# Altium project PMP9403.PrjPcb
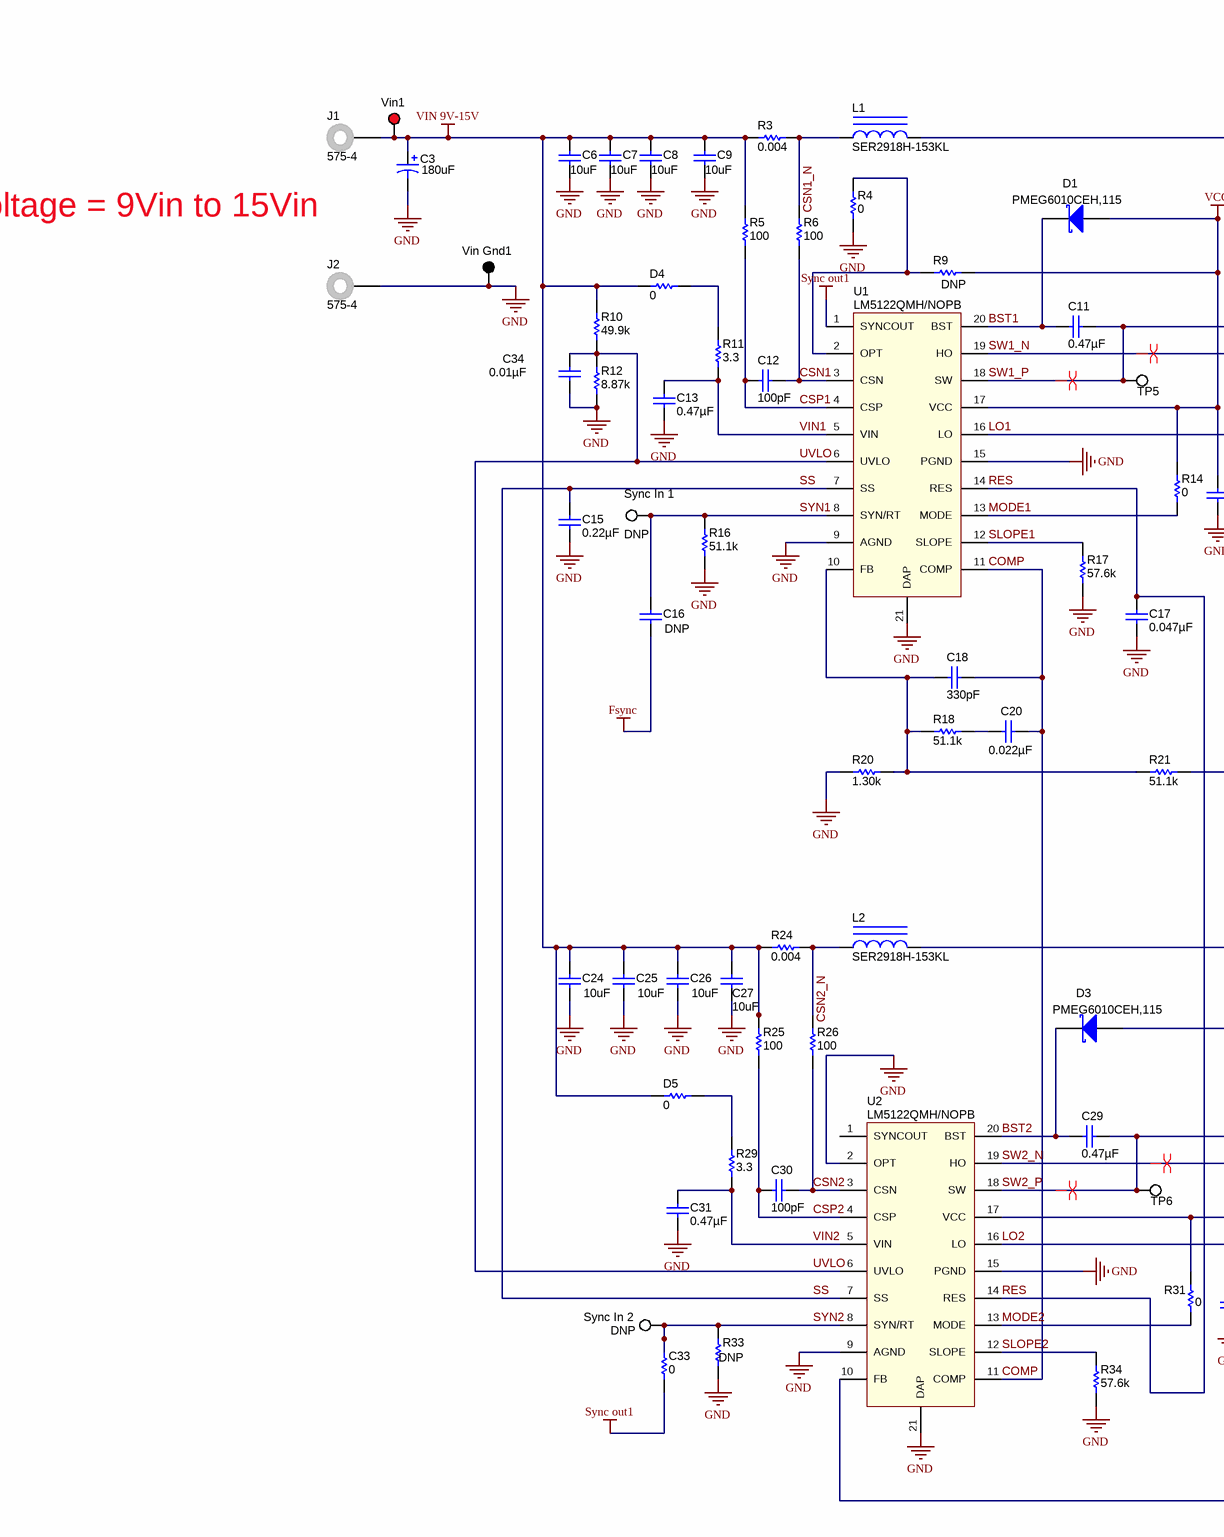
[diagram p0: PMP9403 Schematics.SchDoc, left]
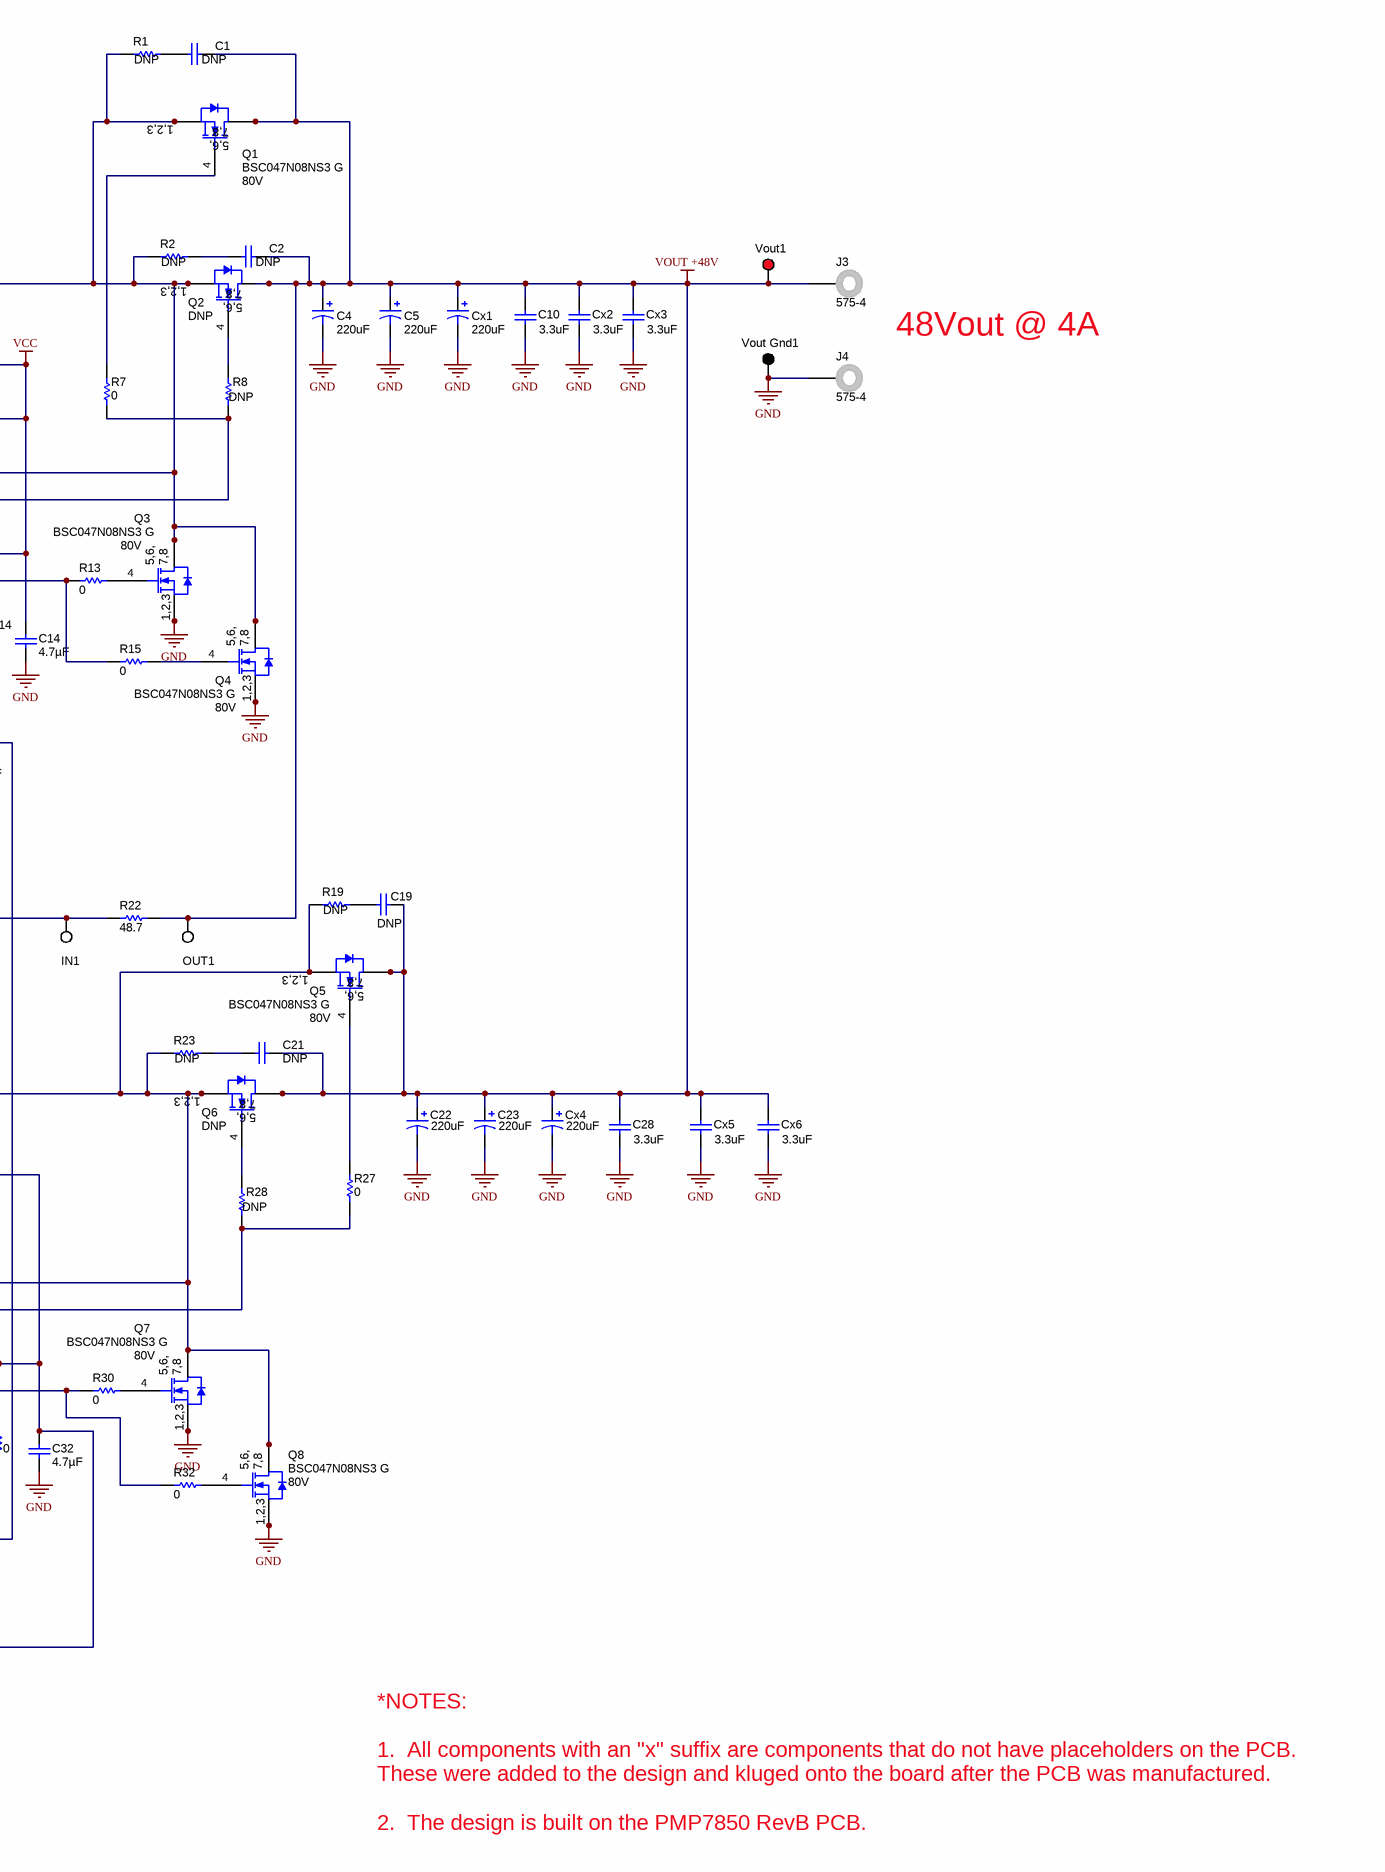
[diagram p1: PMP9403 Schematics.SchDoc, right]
TID: PMP9403; TechSupport: http://www.ti.com/support; SCH_Rev: A; PRJ_Title: LM5122 Dual-Phase Synchronous Boost; PRJ_Number: PMP9403; PRJ_Engineer: Hrag Kasparian; PRJ_Customer: Public Release; PCB_RevB: B; PCB_Layout: N/A; EVM_Orderable: N/A; CopyrightYear: 2015
2 sheets, 113 parts. Net scope: global (net labels, ports and power ports of the same name join across sheets).
Board file: PMP7850 REVB.PcbDoc
Sheets:
  PMP9403 Schematics.SchDoc
  PMP9403_TID_Hardware.SchDoc

## Sheet PMP9403 Schematics.SchDoc: Schematic
size 558 x 431 mm; Date: Not shown in title block; ApprovedBy: Not shown in title block; CheckedBy: Not shown in title block; Author: Not shown in title block; CompanyName: Not shown in title block; Engineer: Not shown in title block; Organization: Not shown in title block; Address1: Not shown in title block; Address2: Not shown in title block; Address3: Not shown in title block; Address4: Not shown in title block; DocumentNumber: 1; Revision: Use project parameter SCH_Rev; SheetNumber: 1; SheetTotal: 2; PageSetup: Record=PageOptions¦CenterHorizontal=True¦CenterVertical=True¦PrintScale=1.00¦XCorrection=1.00¦YCorrection=1.00¦PrintKind=0¦BorderSize=5000000¦LeftOffset=0¦BottomOffset=0¦Orientation=2¦PaperLength=1000¦PaperWidth=1000¦Scale=100¦PaperSource=15¦PrintQuality=600¦MediaType=1¦DitherType=10¦PaperKind=Letter¦PrintScaleMode=1

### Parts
C1  DNP  [0805_HV]
C2  DNP  [0805_HV]
C3  180uF  [TBD]
C4  220uF  [TBD]
C5  220uF  [TBD]
C6  10uF  [TBD]
C7  10uF  [TBD]
C8  10uF  [TBD]
C9  10uF  [TBD]
C10  3.3uF  [TBD]
C11  ValueDisplayed: 0.47µF  [0603_HV]  (hidden comment: GRM188R71E474KA12D)
C12  ValueDisplayed: 100pF  [0603_HV]  (hidden comment: GRM1885C1H101JA01D)
C13  ValueDisplayed: 0.47µF  [0603_HV]  (hidden comment: GRM188R71E474KA12D)
C14  ValueDisplayed: 4.7µF  [0805_HV]  (hidden comment: GRM21BR71C475KA73L)
C15  ValueDisplayed: 0.22µF  [0603]  (hidden comment: GRM188R71E224KA88D)
C16  DNP  [0603_HV]
C17  ValueDisplayed: 0.047µF  [0603_HV]  (hidden comment: GRM188R71E473KA01D)
C18  ValueDisplayed: 330pF  [0603]  (hidden comment: 06035A331JAT2A)
C19  DNP  [0805_HV]
C20  ValueDisplayed: 0.022µF  [0603_HV]  (hidden comment: C0603C223K3RACTU)
C21  DNP  [0805_HV]
C22  220uF  [TBD]
C23  220uF  [TBD]
C24  10uF  [TBD]
C25  10uF  [TBD]
C26  10uF  [TBD]
C27  10uF  [TBD]
C28  3.3uF  [TBD]
C29  ValueDisplayed: 0.47µF  [0603_HV]  (hidden comment: GRM188R71E474KA12D)
C30  ValueDisplayed: 100pF  [0603_HV]  (hidden comment: GRM1885C1H101JA01D)
C31  ValueDisplayed: 0.47µF  [0603_HV]  (hidden comment: GRM188R71E474KA12D)
C32  ValueDisplayed: 4.7µF  [0805_HV]  (hidden comment: GRM21BR71C475KA73L)
C33  value 0  [0603]  (hidden comment: CRCW06030000Z0EA)
C34  ValueDisplayed: 0.01µF  [0603_HV]  (hidden comment: GRM188R71C103KA01D)
Cx1  220uF  [TBD]
Cx2  3.3uF  [TBD]
Cx3  3.3uF  [TBD]
Cx4  220uF  [TBD]
Cx5  3.3uF  [TBD]
Cx6  3.3uF  [TBD]
D1  PMEG6010CEH,115  [SOD-123F]
D3  PMEG6010CEH,115  [SOD-123F]
D4  value 0  [1206]  (hidden comment: CRCW12060000Z0EA)
D5  value 0  [1206]  (hidden comment: CRCW12060000Z0EA)
IN1  5002  [Keystone5002]  (value not drawn)
J1  575-4  [Keystone_575-4]
J2  575-4  [Keystone_575-4]
J3  575-4  [Keystone_575-4]
J4  575-4  [Keystone_575-4]
L1  SER2918H-153KL  [SER2918]
L2  SER2918H-153KL  [SER2918]
OUT1  5002  [Keystone5002]  (value not drawn)
Q1  BSC047N08NS3 G  value 80V  [PG-TDSON-8]
Q2  DNP  [PG-TDSON-8]
Q3  BSC047N08NS3 G  value 80V  [PG-TDSON-8]
Q4  BSC047N08NS3 G  value 80V  [PG-TDSON-8]
Q5  BSC047N08NS3 G  value 80V  [PG-TDSON-8]
Q6  DNP  [PG-TDSON-8]
Q7  BSC047N08NS3 G  value 80V  [PG-TDSON-8]
Q8  BSC047N08NS3 G  value 80V  [PG-TDSON-8]
R1  DNP  [2010M]
R2  DNP  [2010M]
R3  value 0.004  [TBD]  (hidden comment: PMR100HZPFV4L00)
R4  value 0  [0603_HV]  (hidden comment: ERJ-3GEY0R00V)
R5  value 100  [0603_HV]  (hidden comment: CRCW0603100RFKEA)
R6  value 100  [0603_HV]  (hidden comment: CRCW0603100RFKEA)
R7  value 0  [0603_HV]  (hidden comment: ERJ-3GEY0R00V)
R8  DNP  [0603_HV]
R9  DNP  [0603_HV]
R10  value 49.9k  [0603_HV]  (hidden comment: CRCW060349K9FKEA)
R11  value 3.3  [0603_HV]  (hidden comment: CRCW06033R30JNEA)
R12  value 8.87k  [0603]  (hidden comment: CRCW06038K87FKEA)
R13  value 0  [0603_HV]  (hidden comment: ERJ-3GEY0R00V)
R14  value 0  [0603_HV]  (hidden comment: ERJ-3GEY0R00V)
R15  value 0  [0603_HV]  (hidden comment: ERJ-3GEY0R00V)
R16  value 51.1k  [0603]  (hidden comment: CRCW060351K1FKEA)
R17  value 57.6k  [0603]  (hidden comment: CRCW060357K6FKEA)
R18  value 51.1k  [0603]  (hidden comment: CRCW060351K1FKEA)
R19  DNP  [2010M]
R20  value 1.30k  [0603]  (hidden comment: CRCW06031K30FKEA)
R21  value 51.1k  [0603]  (hidden comment: CRCW060351K1FKEA)
R22  value 48.7  [0805_HV]  (hidden comment: CRCW080548R7FKEA)
R23  DNP  [2010M]
R24  value 0.004  [TBD]  (hidden comment: PMR100HZPFV4L00)
R25  value 100  [0603_HV]  (hidden comment: CRCW0603100RFKEA)
R26  value 100  [0603_HV]  (hidden comment: CRCW0603100RFKEA)
R27  value 0  [0603_HV]  (hidden comment: ERJ-3GEY0R00V)
R28  DNP  [0603_HV]
R29  value 3.3  [0603_HV]  (hidden comment: CRCW06033R30JNEA)
R30  value 0  [0603_HV]  (hidden comment: ERJ-3GEY0R00V)
R31  value 0  [0603_HV]  (hidden comment: ERJ-3GEY0R00V)
R32  value 0  [0603_HV]  (hidden comment: ERJ-3GEY0R00V)
R33  DNP  [0603]
R34  value 57.6k  [0603]  (hidden comment: CRCW060357K6FKEA)
Sync_In_1  DNP  [Keystone5002]
Sync_In_2  DNP  [Keystone5002]
TP5  5002  [Keystone5002]  (value not drawn)
TP6  5002  [Keystone5002]  (value not drawn)
U1  LM5122QMH/NOPB  [MXA20A_L - 10milVia]
U2  LM5122QMH/NOPB  [MXA20A_L - 10milVia]
Vin1  5000  [Keystone5000]  (value not drawn)
Vin_Gnd1  5001  [Keystone5001]  (value not drawn)
Vout1  5000  [Keystone5000]  (value not drawn)
Vout_Gnd1  5001  [Keystone5001]  (value not drawn)

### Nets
Fsync: C16.1
GND: C3.2(-) C4.2(-) C5.2(-) C6.2 C7.2 C8.2 C9.2 C10.2 C13.2 C14.2 C15.2 C17.2 C22.2(-) C23.2(-) C24.2 C25.2 C26.2 C27.2 C28.2 C31.2 C32.2 C34.2 Cx1.2(-) Cx2.2 Cx3.2 Cx4.2(-) Cx5.2 Cx6.2 J2.1 J4.1 Q3.1(S) Q3.2(S) Q3.3(S) Q4.1(S) Q4.2(S) Q4.3(S) Q7.1(S) Q7.2(S) Q7.3(S) Q8.1(S) Q8.2(S) Q8.3(S) R4.1 R12.1 R16.1 R17.1 R20.2 R33.1 R34.1 U1.9(AGND) U1.15(PGND) U1.21(DAP) U2.2(OPT) U2.9(AGND) U2.15(PGND) U2.21(DAP) Vin_Gnd1.1 Vout_Gnd1.1
Sync out1: C33.2 U1.1(SYNCOUT)
VCC: C14.1 D1.2(A) R9.2 R14.2 U1.17(VCC)
VIN 9V-15V: C3.1(+) C6.1 C7.1 C8.1 C9.1 C24.1 C25.1 C26.1 C27.1 D4.2 D5.2 J1.1 R3.1 R5.2 R10.2 R24.1 R25.2 Vin1.1
VOUT +48V: C1.1 C2.1 C4.1(+) C5.1(+) C10.1 C19.1 C21.1 C22.1(+) C23.1(+) C28.1 Cx1.1(+) Cx2.1 Cx3.1 Cx4.1(+) Cx5.1 Cx6.1 J3.1 OUT1.1 Q1.5(D) Q1.6(D) Q1.7(D) Q1.8(D) Q1.9(D) Q2.5(D) Q2.6(D) Q2.7(D) Q2.8(D) Q2.9(D) Q5.5(D) Q5.6(D) Q5.7(D) Q5.8(D) Q5.9(D) Q6.5(D) Q6.6(D) Q6.7(D) Q6.8(D) Q6.9(D) R22.1 Vout1.1
BST1: C11.2 D1.1(K) U1.20(BST)
BST2: C29.2 D3.1(K) U2.20(BST)
COMP: C18.2 C20.2 U1.11(COMP) U2.11(COMP)
CSN1: C12.1 R6.1 U1.3(CSN)
CSN1_N: L1.1 R3.2 R6.2
CSN2: C30.1 R26.1 U2.3(CSN)
CSN2_N: L2.1 R24.2 R26.2
CSP1: C12.2 R5.1 U1.4(CSP)
CSP2: C30.2 R25.1 U2.4(CSP)
LO1: R13.2 R15.2 U1.16(LO)
LO2: R30.2 R32.2 U2.16(LO)
MODE1: R14.1 U1.13(MODE)
MODE2: R31.1 U2.13(MODE)
RES: C17.1 U1.14(RES) U2.14(RES)
SLOPE1: R17.2 U1.12(SLOPE)
SLOPE2: R34.2 U2.12(SLOPE)
SS: C15.1 U1.7(SS) U2.7(SS)
SW1_N: R7.2 R8.2 U1.19(HO)
SW1_P: C11.1 L1.2 Q1.1(S) Q1.2(S) Q1.3(S) Q2.1(S) Q2.2(S) Q2.3(S) Q3.5(D) Q3.6(D) Q3.7(D) Q3.8(D) Q3.9(D) Q4.5(D) Q4.6(D) Q4.7(D) Q4.8(D) Q4.9(D) R1.2 R2.2 TP5.1 U1.18(SW)
SW2_N: R27.2 R28.2 U2.19(HO)
SW2_P: C29.1 L2.2 Q5.1(S) Q5.2(S) Q5.3(S) Q6.1(S) Q6.2(S) Q6.3(S) Q7.5(D) Q7.6(D) Q7.7(D) Q7.8(D) Q7.9(D) Q8.5(D) Q8.6(D) Q8.7(D) Q8.8(D) Q8.9(D) R19.2 R23.2 TP6.1 U2.18(SW)
SYN1: C16.2 R16.2 Sync_In_1.1 U1.8(SYN/RT)
SYN2: C33.1 R33.2 Sync_In_2.1 U2.8(SYN/RT)
UVLO: C34.1 R10.1 R12.2 U1.6(UVLO) U2.6(UVLO)
VIN1: C13.1 R11.1 U1.5(VIN)
VIN2: C31.1 R29.1 U2.5(VIN)
NetC1_2: C1.2 R1.1
NetC2_2: C2.2 R2.1
NetC18_1: C18.1 R18.1 R20.1 R21.1 U1.10(FB)
NetC19_2: C19.2 R19.1
NetC20_1: C20.1 R18.2
NetC21_2: C21.2 R23.1
NetC32_1: C32.1 D3.2(A) R31.2 U2.10(FB) U2.17(VCC)
NetD4_1: D4.1 R11.2
NetD5_1: D5.1 R29.2
NetIN1_1: IN1.1 R21.2 R22.2
NetQ1_4: Q1.4(G) R7.1
NetQ2_4: Q2.4(G) R8.1
NetQ3_4: Q3.4(G) R13.1
NetQ4_4: Q4.4(G) R15.1
NetQ5_4: Q5.4(G) R27.1
NetQ6_4: Q6.4(G) R28.1
NetQ7_4: Q7.4(G) R30.1
NetQ8_4: Q8.4(G) R32.1
NetR4_2: R4.2 R9.1 U1.2(OPT)

Not connected (* = marked no-connect by the designer): U2 1(SYNCOUT)

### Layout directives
differential pair: SW1_N, SW1_P, SW2_N, SW2_P

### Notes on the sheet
- 48Vout @ 4A
- Input Voltage = 9Vin to 15Vin
- *NOTES:
  1.  All components with an "x" suffix are components that do not have placeholders on the PCB. These were added to the design and kluged onto the board after the PCB was manufactured.
  2.  The design is built on the PMP7850 RevB PCB.

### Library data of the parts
C1 C2 C19 C21 = GRM2165C2A471JA01D: CAP, CERM, 470pF, 100V, +/-5%, C0G/NP0, 0805; Manufacturer: MuRata; Polarized: N; CompType: Capacitor; U/M: EA; Cap_F: 0.00000000047; Tolerance_%: 5; VDC_V: 100; TaMin_C: -55; TaMax_C: 125; Cap_Case: 0805
C3 = Capacitor_Polarized: CAP, Al Electrolytic, 180uF, 16V, +/-20%, SMT; Manufacturer: Sanyo; PartNumber: 16SVP180MX; Polarized: Y; U/M: EA
C4 C5 C22 C23 Cx1 Cx4 = Capacitor_Polarized: CAP, Al Electrolytic, 220uF, 63V, +/-20%, 0.14Ohm ESR, SMT; Manufacturer: Sanyo; PartNumber: 63CE220KX; Polarized: Y; U/M: EA
C6-C9 C24-C27 = Capacitor: CAP, CERM, 10uF, 25V, X7R, 10%, 1206; Manufacturer: Samsung; PartNumber: CL31B106KAHNNNB; Polarized: N; U/M: EA
C10 C28 Cx2 Cx3 Cx5 Cx6 = Capacitor: CAP, CERM, 3.3uF, 50V, X7R, 10%, 1210; Manufacturer: Murata; PartNumber: GRM32DR71H335KA88L; Polarized: N; U/M: EA
C11 C13 C29 C31 = GRM188R71E474KA12D: CAP, CERM, 0.47uF, 25V, +/-10%, X7R, 0603; Manufacturer: MuRata; Polarized: N; CompType: Capacitor; U/M: EA; Cap_F: 0.00000047; Tolerance_%: 10; VDC_V: 25; TaMin_C: -55; TaMax_C: 125; Cap_Case: 0603
C12 C16 C30 = GRM1885C1H101JA01D: CAP, CERM, 100pF, 50V, +/-5%, C0G/NP0, 0603; Manufacturer: MuRata; Polarized: N; CompType: Capacitor; U/M: EA; Cap_F: 0.0000000001; Tolerance_%: 5; VDC_V: 50; TaMin_C: -55; TaMax_C: 125; Cap_Case: 0603
C14 C32 = GRM21BR71C475KA73L: CAP, CERM, 4.7uF, 16V, +/-10%, X7R, 0805; Manufacturer: MuRata; Polarized: N; CompType: Capacitor; U/M: EA; Cap_F: 0.0000047; Tolerance_%: 10; ESR_Ohm: 0.006; Value1: 0.006 ohm; VDC_V: 16; TaMin_C: -55; TaMax_C: 125; Cap_Case: 0805
C15 = GRM188R71E224KA88D: CAP, CERM, 0.22uF, 25V, +/-10%, X7R, 0603; Manufacturer: MuRata; Polarized: N; CompType: Capacitor; U/M: EA; Cap_F: 0.00000022; Tolerance_%: 10; Value1: Unknown; VDC_V: 25; TaMin_C: -55; TaMax_C: 125
C17 = GRM188R71E473KA01D: CAP, CERM, 0.047uF, 25V, +/-10%, X7R, 0603; Manufacturer: MuRata; Polarized: N; CompType: Capacitor; U/M: EA; Cap_F: 0.000000047; Tolerance_%: 10; VDC_V: 25; TaMin_C: -55; TaMax_C: 125; Cap_Case: 0603
C18 = 06035A331JAT2A: CAP, CERM, 330pF, 50V, +/-5%, C0G/NP0, 0603; Manufacturer: AVX; Polarized: N; CompType: Capacitor; U/M: EA; Cap_F: 0.00000000033; Tolerance_%: 5; ESR_Ohm: 0.071; Value1: 0.071 ohm; VDC_V: 50; TaMin_C: -55; TaMax_C: 125
C20 = C0603C223K3RACTU: CAP, CERM, 0.022uF, 25V, +/-10%, X7R, 0603; Manufacturer: Kemet; Polarized: N; CompType: Capacitor; U/M: EA; Cap_F: 0.000000022; Tolerance_%: 10; VDC_V: 25; TaMin_C: -55; TaMax_C: 125; Cap_Case: 0603
C33 = CRCW06030000Z0EA: RES, 0 ohm, 5%, 0.1W, 0603; Manufacturer: Vishay-Dale; CompType: Resistor; U/M: EA; Tolerance_%: 5; VDC_V: 75; TempCo: 200 ppm/C; Value_Code: 0000; Power_W: 0.1; EIA_Code: E24
C34 = GRM188R71C103KA01D: CAP, CERM, 0.01uF, 16V, +/-10%, X7R, 0603; Manufacturer: MuRata; Polarized: N; CompType: Capacitor; U/M: EA; Cap_F: 0.00000001; Tolerance_%: 10; VDC_V: 16; TaMin_C: -55; TaMax_C: 125; Cap_Case: 0603
D1 D3 = PMEG6010CEH,115: Diode, Schottky, 60V, 1A, SOD-123F; Manufacturer: NXP Semiconductor; U/M: EA; Vf_V: 0.57; Io_A: 1; Vr_V: 60; TJmax_C: 150; Value: 0.57V
D4 D5 = CRCW12060000Z0EA: RES, 0 ohm, 5%, 0.25W, 1206; Manufacturer: Vishay-Dale; CompType: Resistor; U/M: EA; Value_Code: 0000; Tolerance_%: 5; Power_W: 0.25; VDC_V: 200; TempCo: 200 ppm/C; EIA_Code: E24
IN1 OUT1 Sync_In_1 Sync_In_2 TP5 TP6 = 5002: Test Point, TH, Miniature, White; Manufacturer: Keystone; Alternate Manufacturer: Any; Alternate PartNumber: Equivalent; CompType: Test Point Loop; U/M: EA
J1-J4 = 575-4: Standard Banana Jack, Uninsulated, 5.5mm; Manufacturer: Keystone; Alternate Manufacturer: Any; Alternate PartNumber: Equivalent; CompType: Connector; U/M: EA
L1 L2 = SER2918H-153KL: Inductor, Shielded E Core, Ferrite, 15uH, 21.9A, 0.0026 ohm, SMD; Manufacturer: Coilcraft; ValueDisplayed: 15µH; Ind_H: 15.0E-6; Imax_A: 21.9; Irms: 28A @ 40C rise; Isat: 21.9A @ 30% inductance drop; DCR_ohm: 0.0026; U/M: EA
Q1-Q8 = BSC047N08NS3 G: MOSFET, N-CH, 80V, 100A, PG-TDSON-8; Manufacturer: Infineon Technologies; Alternate Manufacturer: None; U/M: EA; ChType: N; VdsMax_V: 80; Value1: 101 ohm; Rdson45_Ohm: 101; Value2: 52 nC; QgTyp_nC: 52; Vgs_V: 20; IdsMax_A: 100
R1 R2 R19 R23 = ERJ-12ZYJ7R5U: RESISTOR 7.5 OHM 3/4W 5% 2010; Manufacturer: Panasonic; Value: 7.5; Value_Code: 7R50; Tolerance_%: 5; Power_W: 1; Value2: 1W; VDC_V: 3; TempCo: -100 /+600 ppm/C; EIA_Code: E24; U/M: EA
R3 R24 = Resistor: RES, 0.004 ohm, 1%, 2W, 2512; Manufacturer: Rohm Semiconductor; U/M: EA
R4 R7 R13-R15 R27 R30-R32 = ERJ-3GEY0R00V: RES, 0 ohm, 5%, 0.1W, 0603; Manufacturer: Panasonic; CompType: Resistor; Value_Code: 0000; Tolerance_%: 5; Power_W: 0.1; VDC_V: 50; TempCo: 600 ppm/C; EIA_Code: E24; U/M: EA
R5 R6 R25 R26 = CRCW0603100RFKEA: RES, 100 ohm, 1%, 0.1W, 0603; Manufacturer: Vishay-Dale; CompType: Resistor; Value_Code: 100R; Tolerance_%: 1; Power_W: 0.1; VDC_V: 75; TempCo: 100 ppm/C; EIA_Code: E96; U/M: EA
R8 R28 = ERJ-3GEY0R00V: RES, 0 ohm, 5%, 0.1W, 0603; Manufacturer: Panasonic; CompType: Resistor; Value: 0; Value_Code: 0000; Tolerance_%: 5; Power_W: 0.1; VDC_V: 50; TempCo: 600 ppm/C; EIA_Code: E24; U/M: EA
R9 = CRCW0603158KFKEA: RES, 158k ohm, 1%, 0.1W, 0603; Manufacturer: Vishay-Dale; CompType: Resistor; Res_ohm: 158000; Tolerance_%: 1; Power_W: 0.1; VDC_V: 75; TempCo: 100 ppm/C; EIA_Code: E96; U/M: EA
R10 = CRCW060349K9FKEA: RES, 49.9k ohm, 1%, 0.1W, 0603; Manufacturer: Vishay-Dale; CompType: Resistor; Res_ohm: 49900; Value_Code: 49k9; Tolerance_%: 1; Power_W: 0.1; VDC_V: 75; TempCo: 100 ppm/C; EIA_Code: E96; U/M: EA
R11 R29 = CRCW06033R30JNEA: RES, 3.3 ohm, 5%, 0.1W, 0603; Manufacturer: Vishay-Dale; CompType: Resistor; Value_Code: 3R30; Tolerance_%: 5; Power_W: 0.1; VDC_V: 75; TempCo: 200 ppm/C; EIA_Code: E24; U/M: EA
R12 = CRCW06038K87FKEA: RES, 8.87k ohm, 1%, 0.1W, 0603; Manufacturer: Vishay-Dale; CompType: Resistor; Res_ohm: 8870; Value_Code: 8k87; Tolerance_%: 1; Power_W: 0.1; VDC_V: 75; TempCo: 100 ppm/C; EIA_Code: E96; U/M: EA
R16 R18 R21 = CRCW060351K1FKEA: RES, 51.1k ohm, 1%, 0.1W, 0603; Manufacturer: Vishay-Dale; CompType: Resistor; Res_ohm: 51100; Value_Code: 51k1; Tolerance_%: 1; Power_W: 0.1; VDC_V: 75; TempCo: 100 ppm/C; EIA_Code: E96; U/M: EA
R17 R34 = CRCW060357K6FKEA: RES, 57.6k ohm, 1%, 0.1W, 0603; Manufacturer: Vishay-Dale; CompType: Resistor; Res_ohm: 57600; Value_Code: 57k6; Tolerance_%: 1; Power_W: 0.1; VDC_V: 75; TempCo: 100 ppm/C; EIA_Code: E96; U/M: EA
R20 = CRCW06031K30FKEA: RES, 1.30k ohm, 1%, 0.1W, 0603; Manufacturer: Vishay-Dale; CompType: Resistor; Res_ohm: 1300; Value_Code: 1k30; Tolerance_%: 1; Power_W: 0.1; VDC_V: 75; TempCo: 100 ppm/C; EIA_Code: E96; U/M: EA
R22 = CRCW080548R7FKEA: RES, 48.7 ohm, 1%, 0.125W, 0805; Manufacturer: Vishay-Dale; CompType: Resistor; Value_Code: 48R7; Tolerance_%: 1; Power_W: 0.125; VDC_V: 150; TempCo: 100 ppm/C; EIA_Code: E96; U/M: EA
R33 = CRCW060320K0FKEA: RES, 20.0k ohm, 1%, 0.1W, 0603; Manufacturer: Vishay-Dale; CompType: Resistor; Res_ohm: 20000; Value_Code: 20k0; Tolerance_%: 1; Power_W: 0.1; VDC_V: 75; TempCo: 100 ppm/C; EIA_Code: E96; U/M: EA
U1 U2 = LM5122: Manufacturer: Texas Instruments; SymbolCreator: bkinsc; CompType: IC; U/M: EA
Vin1 Vout1 = 5000: Test Point, TH, Miniature, Red; Manufacturer: Keystone; CompType: Test Point Loop; U/M: EA
Vin_Gnd1 Vout_Gnd1 = 5001: Test Point, TH, Miniature, Black; Manufacturer: Keystone; CompType: Test Point Loop; U/M: EA

## Sheet PMP9403_TID_Hardware.SchDoc: Hardware
size 431 x 279 mm; Date: Not shown in title block; ApprovedBy: Not shown in title block; CheckedBy: Not shown in title block; Author: Not shown in title block; CompanyName: Not shown in title block; Engineer: Not shown in title block; Organization: Not shown in title block; Address1: Not shown in title block; Address2: Not shown in title block; Address3: Not shown in title block; Address4: Not shown in title block; DocumentNumber: 2; Revision: Use project parameter SCH_Rev; SheetNumber: 2; SheetTotal: 2; PageSetup: Record=PageOptions¦CenterHorizontal=True¦CenterVertical=True¦PrintScale=1.00¦XCorrection=1.00¦YCorrection=1.00¦PrintKind=0¦BorderSize=5000000¦LeftOffset=0¦BottomOffset=0¦Orientation=2¦PaperLength=1000¦PaperWidth=1000¦Scale=100¦PaperSource=15¦PrintQuality=600¦MediaType=1¦DitherType=10¦PaperKind=Letter¦PrintScaleMode=1
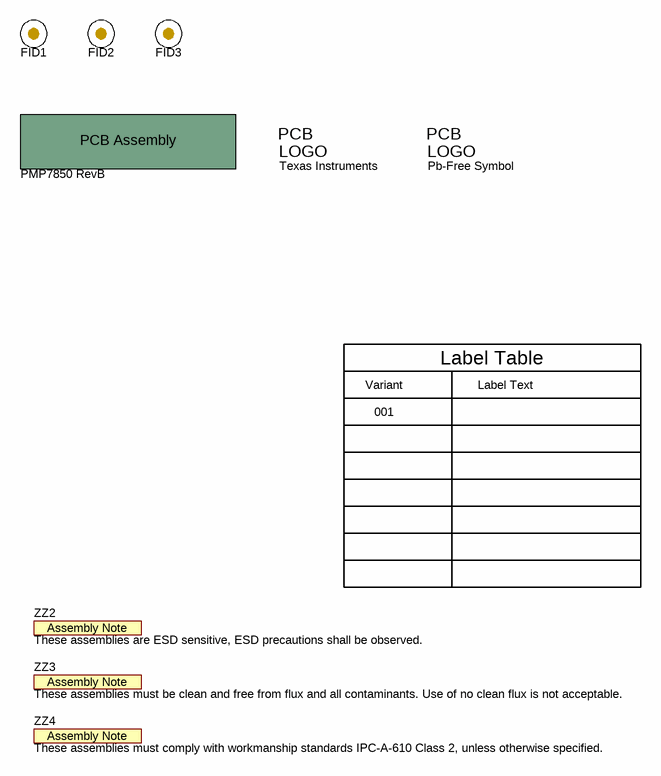
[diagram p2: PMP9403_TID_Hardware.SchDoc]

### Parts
!PCBA1  PartNumber: PMP7850 RevB  (hidden comment: PMP7850 RevB PCB)  (mechanical)
FID1  Fiducial  [Fiducial10-20]  (value not drawn)
FID2  Fiducial  [Fiducial10-20]  (value not drawn)
FID3  Fiducial  [Fiducial10-20]  (value not drawn)
Logo1  Texas Instruments  [TI_Stacked_SolderMask_Small]  (no BOM)
Logo2  Pb-Free Symbol  [Pb-Free_Overlay_Small]  (no BOM)
ZZ2  These assemblies are ESD sensitive, ESD precautions shall be observed.  [AssemblyNote]  (no BOM)
ZZ3  These assemblies must be clean and free from flux and all contaminants. Use of no clean flux is not acceptable.  [AssemblyNote]  (no BOM)
ZZ4  These assemblies must comply with workmanship standards IPC-A-610 Class 2, unless otherwise specified.  [AssemblyNote]  (no BOM)

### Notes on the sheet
- Variant
- Label Table
- Label Text
- 001

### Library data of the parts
!PCBA1 = PCBA: Manufacturer: Any; SymbolCreator: a0412235; U/M: EA
FID1-FID3 = Fiducial: Fiducial mark.  There is nothing to buy or mount.; SymbolCreator: codlsc
Logo1 = TI_Logo: Texas Instrument Corporate Signature; SymbolCreator: codlsc
Logo2 = Pb-Free: SymbolCreator: a0412235
ZZ2-ZZ4 = AssemblyNote: SymbolCreator: codlsc

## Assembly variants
001: not fitted C1 C2 C16 C19 C21 Q2 Q6 R1 R2 R8 R9 R19 R23 R28 R33 Sync In 1 Sync In 2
